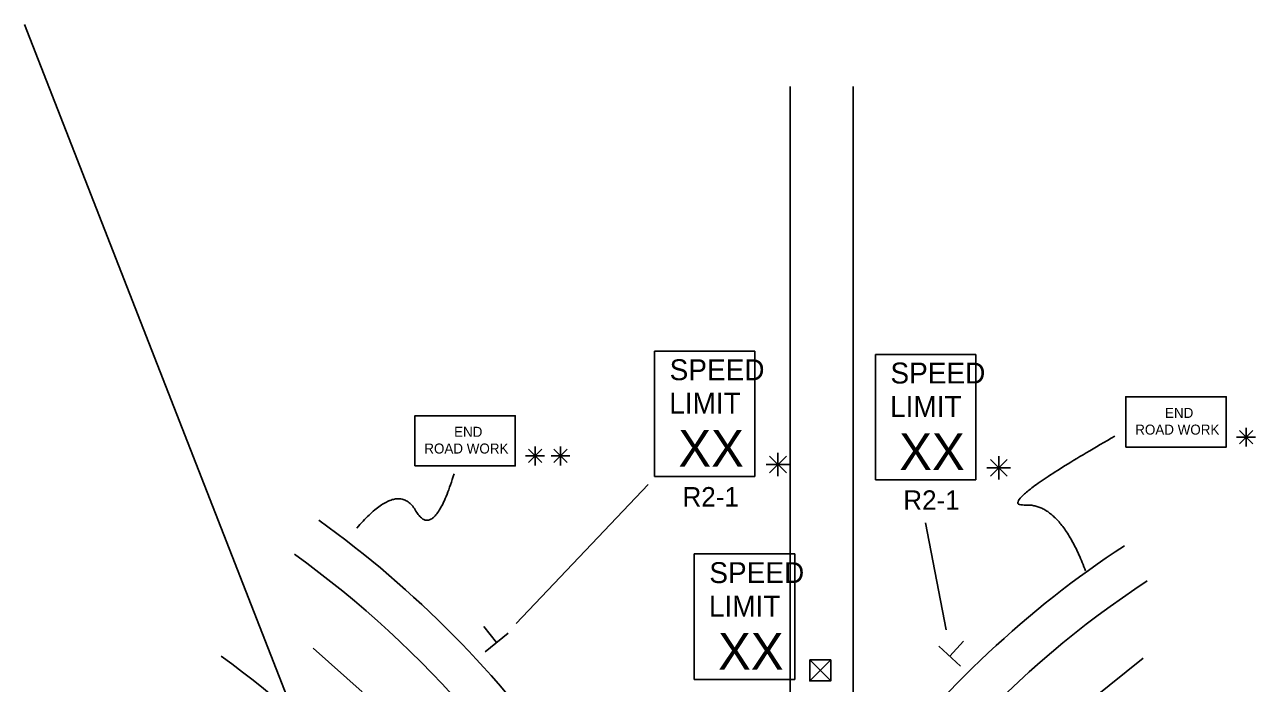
# Model space of a CAD drawing. Extents: x 16630 to 19509, y 5576 to 6998.
# Drawn here: x 16688.1 to 17158.5, y 6745.9 to 6997.8 of the extents above; entities that cross this region are included whole.
import ezdxf

# ---------------------------------------------------------------- set-up
doc = ezdxf.new("R2010")
doc.units = 0
for name, color, linetype in [('ALI_LEGAL_EX', 7, 'Continuous'), ('PAVT_EDGE_EX', 7, 'Continuous'), ('TRAFFIC_SIGNS_PR', 7, 'Continuous'), ('TYPICAL_TEXT_DIMEN_PR', 7, 'Continuous')]:
    doc.layers.add(name, color=color, linetype=linetype)

msp = doc.modelspace()

# ---------------------------------------------------------------- linework, layer by layer
at = {"layer": 'ALI_LEGAL_EX'}
for p, q in [((16688.08, 6997.81), (16910.11, 6429.44)), ((16980.68, 6974.12), (16980.68, 6155.98)), ((17004.68, 6974.12), (17004.68, 6155.98)), ((16980.68, 6922.21), (16980.68, 6058.3)), ((17004.68, 6922.21), (17004.68, 6058.3))]:
    msp.add_line(p, q, dxfattribs=at)
for points in [[(17004.68, 6949.12), (17004.68, 6974.12)], [(16817.07, 6742.72), (16798.4, 6759.35)], [(17096.1, 6739.95), (17115.56, 6755.65)]]:
    msp.add_lwpolyline(points, dxfattribs=at)
at = {"layer": 'PAVT_EDGE_EX'}
for centre, radius, start, end in [((16564.4, 6480.53), 404, 15.917, 54.2283), ((17316.4, 6480.53), 380, 123.1879, 163.0483), ((16564.4, 6480.53), 388, 0, 54.2283), ((17316.4, 6480.53), 364, 123.1879, 180), ((16564.4, 6480.53), 340, 0, 54.2283)]:
    msp.add_arc(centre, radius, start, end, dxfattribs=at)
at = {"layer": 'TRAFFIC_SIGNS_PR'}
for p, q in [((16928.82, 6873), (16967.22, 6873)), ((16928.82, 6825), (16928.82, 6873)), ((16967.22, 6825), (16967.22, 6873)), ((17013.23, 6871.74), (17051.63, 6871.74)), ((17013.23, 6823.74), (17013.23, 6871.74)), ((17051.63, 6823.74), (17051.63, 6871.74)), ((16928.82, 6825), (16967.22, 6825)), ((17013.23, 6823.74), (17051.63, 6823.74)), ((16944, 6795.43), (16982.4, 6795.43)), ((16944, 6747.43), (16944, 6795.43)), ((16982.4, 6747.43), (16982.4, 6795.43)), ((16944, 6747.43), (16982.4, 6747.43))]:
    msp.add_line(p, q, dxfattribs=at)
for points in [[(17108.93, 6836.31), (17147.33, 6836.31), (17147.33, 6855.51), (17108.93, 6855.51)], [(16837.22, 6829.08), (16875.62, 6829.08), (16875.62, 6848.28), (16837.22, 6848.28)]]:
    msp.add_lwpolyline(points, close=True, dxfattribs=at)
at = {"layer": 'TYPICAL_TEXT_DIMEN_PR'}
for p, q in [((17154.88, 6840.13), (17151.25, 6840.13)), ((17152.33, 6842.68), (17157.43, 6837.58)), ((17157.43, 6842.68), (17152.33, 6837.58)), ((17154.88, 6840.13), (17154.88, 6843.69)), ((17154.88, 6840.13), (17157.43, 6840.13)), ((17154.88, 6840.13), (17158.46, 6840.13)), ((17154.88, 6840.13), (17154.88, 6836.53)), ((16880.62, 6835.45), (16885.72, 6830.35)), ((16885.72, 6835.45), (16880.62, 6830.35)), ((16883.17, 6832.9), (16883.17, 6836.46)), ((16890.37, 6835.45), (16895.47, 6830.35)), ((16895.47, 6835.45), (16890.37, 6830.35)), ((16892.92, 6832.9), (16892.92, 6836.46)), ((16883.17, 6832.9), (16879.55, 6832.9)), ((16883.17, 6832.9), (16885.72, 6832.9)), ((16883.17, 6832.9), (16886.76, 6832.9)), ((16883.17, 6832.9), (16883.17, 6829.3)), ((16892.92, 6832.9), (16889.29, 6832.9)), ((16892.92, 6832.9), (16895.47, 6832.9)), ((16892.92, 6832.9), (16896.5, 6832.9)), ((16892.92, 6832.9), (16892.92, 6829.3)), ((16972.82, 6832.8), (16979.2, 6826.43)), ((16979.2, 6832.8), (16972.82, 6826.43)), ((16976.01, 6829.62), (16976.01, 6834.07)), ((17057.23, 6831.54), (17063.6, 6825.16)), ((17063.6, 6831.54), (17057.23, 6825.16)), ((17060.42, 6828.35), (17060.42, 6832.81)), ((16976.01, 6829.62), (16971.48, 6829.62)), ((16976.01, 6829.62), (16979.2, 6829.62)), ((16976.01, 6829.62), (16980.49, 6829.62)), ((16976.01, 6829.62), (16976.01, 6825.12)), ((17060.42, 6828.35), (17055.88, 6828.35)), ((17060.42, 6828.35), (17063.6, 6828.35)), ((17060.42, 6828.35), (17064.89, 6828.35)), ((17060.42, 6828.35), (17060.42, 6823.85)), ((16926.42, 6822.03), (16875.94, 6768.85)), ((17040.24, 6766.41), (17032.44, 6807.29)), ((16868.44, 6761.57), (16863.56, 6767.65)), ((16872.82, 6765.09), (16864.05, 6758.06)), ((17045.78, 6752.57), (17037.54, 6760.22)), ((17041.66, 6756.39), (17046.96, 6762.1)), ((16988.15, 6754.9), (16996.15, 6746.9)), ((16988.15, 6746.9), (16996.15, 6754.9))]:
    msp.add_line(p, q, dxfattribs=at)
msp.add_lwpolyline([(16988.15, 6754.9), (16988.15, 6746.9), (16996.15, 6746.9), (16996.15, 6754.9)], close=True, dxfattribs=at)
for points in [[(17093.59, 6788.93), (17083.76, 6814.92), (17057.37, 6813.3), (17104.79, 6840.5)], [(16815.05, 6805.35), (16830.8, 6823.7), (16844.29, 6800.22), (16852.21, 6826.08)]]:
    msp.add_open_spline(points, degree=2, dxfattribs=at)

# ---------------------------------------------------------------- texts
at = {"layer": 'TRAFFIC_SIGNS_PR'}
for s, height, p in [('SPEED', 8, (16934.59, 6861.86)), ('SPEED', 8, (17018.99, 6860.6)), ('LIMIT', 8, (16934.43, 6849.06)), ('LIMIT', 8, (17018.83, 6847.8)), ('END', 3.831, (17123.93, 6847.44)), ('ROAD WORK', 3.831, (17112.54, 6841.05)), ('END', 3.831, (16852.22, 6840.21)), ('XX', 14.031, (16937.93, 6828.76)), ('XX', 14.031, (17022.34, 6827.49)), ('ROAD WORK', 3.831, (16840.83, 6833.82)), ('R2-1', 7.44, (16939.5, 6813.56)), ('R2-1', 7.44, (17023.9, 6812.3)), ('SPEED', 8, (16949.76, 6784.29)), ('LIMIT', 8, (16949.6, 6771.49)), ('XX', 14.031, (16953.11, 6751.19))]:
    msp.add_text(s, height=height, dxfattribs=at).set_placement(p)

doc.saveas('drawing.dxf')
